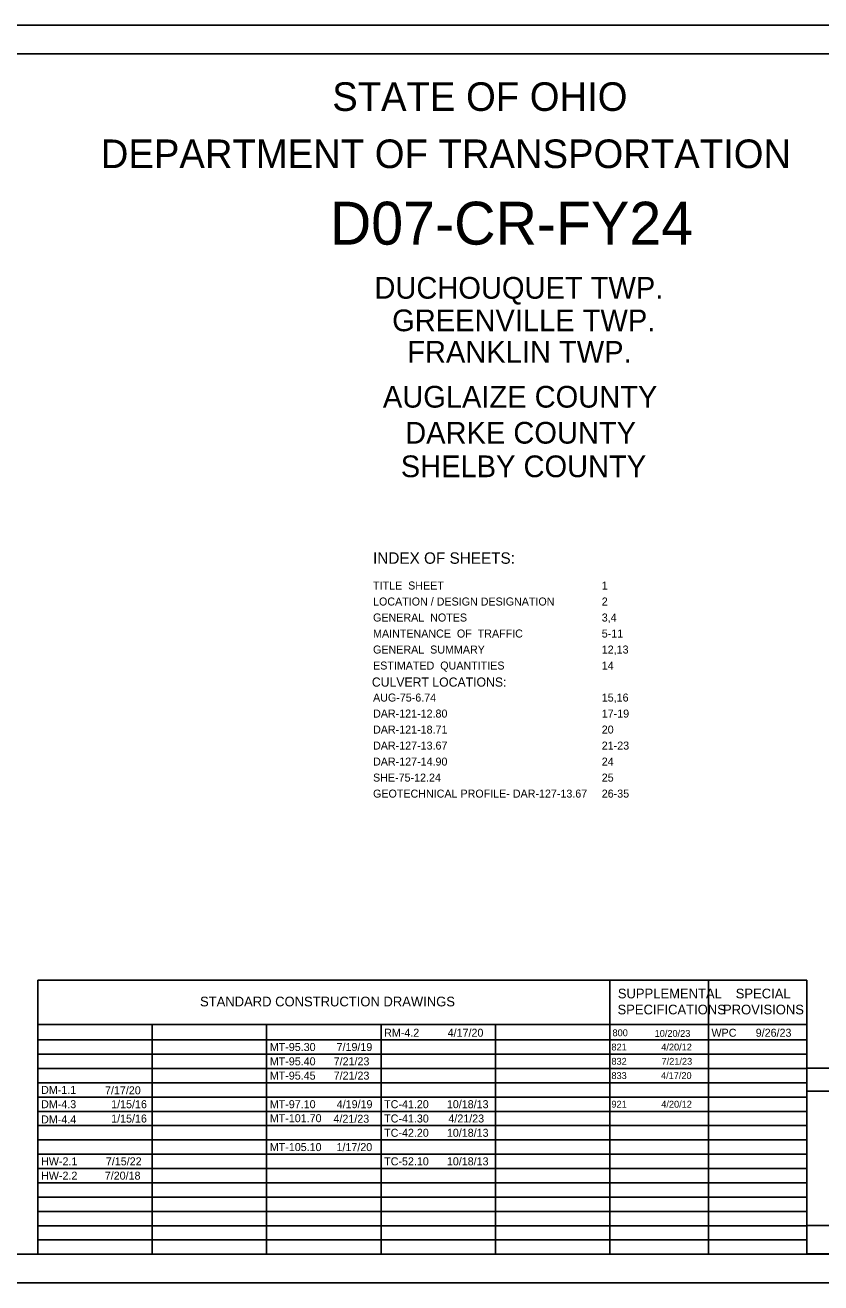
# Model space of a CAD drawing. Extents: x 0 to 34, y 0 to 22.
# Drawn here: x 8.42 to 22.34, y 0 to 22 of the extents above; entities that cross this region are included whole.
import ezdxf

# ---------------------------------------------------------------- set-up
doc = ezdxf.new("R2010")
doc.units = 0
for name, color, linetype in [('SH_Border', 7, 'Continuous'), ('SH_Cut_Line', 7, 'Continuous'), ('SH_Data', 7, 'Continuous'), ('SH_Text', 7, 'Continuous')]:
    doc.layers.add(name, color=color, linetype=linetype)

msp = doc.modelspace()

# ---------------------------------------------------------------- linework, layer by layer
at = {"layer": 'SH_Border'}
msp.add_lwpolyline([(1.5, 21.5), (33.5, 21.5), (33.5, 0.5), (1.5, 0.5)], close=True, dxfattribs=at)
at = {"layer": 'SH_Cut_Line'}
msp.add_lwpolyline([(0, 0), (34, 0), (34, 22), (0, 22)], close=True, dxfattribs=at)
at = {"layer": 'SH_Data'}
for p, q in [((8.648, 5.292), (22.098, 5.292)), ((8.648, 0.5), (8.648, 5.292)), ((8.648, 5.292), (22.098, 5.292)), ((8.648, 0.5), (8.648, 5.292)), ((18.648, 0.5), (18.648, 5.292)), ((18.648, 0.5), (18.648, 5.292)), ((20.373, 0.5), (20.373, 5.292)), ((20.373, 0.5), (20.373, 5.292)), ((22.098, 0.5), (22.098, 5.292)), ((22.098, 0.5), (22.098, 5.292)), ((8.648, 4.521), (22.098, 4.521)), ((8.648, 4.521), (22.098, 4.521)), ((10.648, 0.5), (10.648, 4.521)), ((10.648, 0.5), (10.648, 4.521)), ((12.648, 0.5), (12.648, 4.521)), ((12.648, 0.5), (12.648, 4.521)), ((14.648, 0.5), (14.648, 4.521)), ((14.648, 0.5), (14.648, 4.521)), ((16.648, 0.5), (16.648, 4.521)), ((16.648, 0.5), (16.648, 4.521)), ((8.648, 4.25), (22.098, 4.25)), ((8.648, 4.25), (22.098, 4.25)), ((8.648, 4), (22.098, 4)), ((8.648, 4), (22.098, 4)), ((8.648, 3.75), (22.098, 3.75)), ((8.648, 3.75), (22.098, 3.75)), ((22.098, 0.505), (22.098, 3.755)), ((22.098, 3.755), (24.898, 3.755)), ((8.648, 3.5), (22.098, 3.5)), ((8.648, 3.5), (22.098, 3.5)), ((22.098, 3.355), (24.898, 3.355)), ((8.648, 3.25), (22.098, 3.25)), ((8.648, 3.25), (22.098, 3.25)), ((8.648, 3), (22.098, 3)), ((8.648, 3), (22.098, 3)), ((8.648, 2.75), (22.098, 2.75)), ((8.648, 2.75), (22.098, 2.75)), ((8.648, 2.5), (22.098, 2.5)), ((8.648, 2.5), (22.098, 2.5)), ((8.648, 2.25), (22.098, 2.25)), ((8.648, 2.25), (22.098, 2.25)), ((8.648, 2), (22.098, 2)), ((8.648, 2), (22.098, 2)), ((8.648, 1.75), (22.098, 1.75)), ((8.648, 1.75), (22.098, 1.75)), ((8.648, 1.5), (22.098, 1.5)), ((8.648, 1.5), (22.098, 1.5)), ((8.648, 1.25), (22.098, 1.25)), ((8.648, 1.25), (22.098, 1.25)), ((8.648, 1), (22.098, 1)), ((8.648, 1), (22.098, 1)), ((8.648, 0.75), (22.098, 0.75)), ((8.648, 0.75), (22.098, 0.75)), ((22.098, 0.505), (24.898, 0.505))]:
    msp.add_line(p, q, dxfattribs=at)
msp.add_lwpolyline([(22.098, 0.505), (22.098, 1.005), (24.898, 1.005), (24.898, 0.505)], close=True, dxfattribs=at)

# ---------------------------------------------------------------- texts
for s, height, p in [('RM-4.2', 0.14, (14.703, 4.305)), ('4/17/20', 0.14, (15.814, 4.305)), ('800', 0.12, (18.697, 4.314)), ('10/20/23', 0.12, (19.434, 4.303)), ('WPC', 0.14, (20.428, 4.305)), ('9/26/23', 0.14, (21.202, 4.305)), ('MT-95.30', 0.14, (12.703, 4.055)), ('7/19/19', 0.14, (13.871, 4.055)), ('821', 0.12, (18.678, 4.065)), ('4/20/12', 0.12, (19.55, 4.065)), ('MT-95.40', 0.14, (12.703, 3.805)), ('7/21/23', 0.14, (13.82, 3.805)), ('832', 0.12, (18.678, 3.815)), ('7/21/23', 0.12, (19.555, 3.815)), ('MT-95.45', 0.14, (12.703, 3.555)), ('7/21/23', 0.14, (13.82, 3.555)), ('833', 0.12, (18.678, 3.565)), ('4/17/20', 0.12, (19.545, 3.565)), ('7/17/20', 0.14, (9.821, 3.298)), ('DM-4.3', 0.14, (8.703, 3.055)), ('1/15/16', 0.14, (9.929, 3.055)), ('MT-97.10', 0.14, (12.703, 3.055)), ('4/19/19', 0.14, (13.874, 3.055)), ('TC-41.20', 0.14, (14.703, 3.055)), ('10/18/13', 0.14, (15.8, 3.055)), ('921', 0.12, (18.678, 3.065)), ('4/20/12', 0.12, (19.55, 3.065)), ('DM-4.4', 0.14, (8.703, 2.789)), ('1/15/16', 0.14, (9.929, 2.804)), ('MT-101.70', 0.14, (12.703, 2.81)), ('4/21/23', 0.14, (13.817, 2.801)), ('TC-41.30', 0.14, (14.703, 2.805)), ('4/21/23', 0.14, (15.827, 2.805)), ('TC-42.20', 0.14, (14.703, 2.555)), ('10/18/13', 0.14, (15.8, 2.555)), ('MT-105.10', 0.14, (12.703, 2.305)), ('1/17/20', 0.14, (13.87, 2.305)), ('7/15/22', 0.14, (9.836, 2.055)), ('10/18/13', 0.14, (15.8, 2.055)), ('HW-2.1', 0.14, (8.703, 2.055)), ('TC-52.10', 0.14, (14.703, 2.055)), ('HW-2.2', 0.14, (8.703, 1.805)), ('7/20/18', 0.14, (9.817, 1.805))]:
    msp.add_text(s, height=height, dxfattribs=at).set_placement(p)
at = {"layer": 'SH_Text'}
for s, height, p in [('STATE OF OHIO', 0.5, (13.795, 20.5)), ('STATE OF OHIO', 0.5, (13.795, 20.5)), ('DEPARTMENT OF TRANSPORTATION', 0.5, (9.747, 19.5)), ('DEPARTMENT OF TRANSPORTATION', 0.5, (9.747, 19.5)), ('D07-CR-FY24', 0.75, (13.753, 18.161)), ('DUCHOUQUET TWP.', 0.38, (14.533, 17.215)), ('GREENVILLE TWP.', 0.38, (14.843, 16.646)), ('FRANKLIN TWP.', 0.38, (15.107, 16.095)), ('AUGLAIZE COUNTY', 0.38, (14.681, 15.31)), ('DARKE COUNTY', 0.38, (15.071, 14.68)), ('SHELBY COUNTY', 0.38, (14.994, 14.093)), ('INDEX OF SHEETS:', 0.2, (14.509, 12.578)), ('INDEX OF SHEETS:', 0.2, (14.509, 12.578)), ('TITLE  SHEET', 0.14, (14.509, 12.128)), ('1', 0.14, (18.509, 12.128)), ('LOCATION / DESIGN DESIGNATION', 0.14, (14.509, 11.848)), ('2', 0.14, (18.509, 11.848)), ('GENERAL  NOTES', 0.14, (14.509, 11.568)), ('3,4', 0.14, (18.509, 11.568)), ('MAINTENANCE  OF  TRAFFIC', 0.14, (14.509, 11.288)), ('5-11', 0.14, (18.509, 11.288)), ('GENERAL  SUMMARY', 0.14, (14.509, 11.008)), ('12,13', 0.14, (18.509, 11.008)), ('ESTIMATED  QUANTITIES', 0.14, (14.509, 10.728)), ('14', 0.14, (18.509, 10.728)), ('CULVERT LOCATIONS: ', 0.16, (14.488, 10.429)), ('AUG-75-6.74', 0.14, (14.509, 10.168)), ('15,16', 0.14, (18.509, 10.168)), ('DAR-121-12.80', 0.14, (14.509, 9.888)), ('17-19', 0.14, (18.509, 9.888)), ('DAR-121-18.71', 0.14, (14.509, 9.608)), ('20', 0.14, (18.509, 9.608)), ('DAR-127-13.67', 0.14, (14.509, 9.328)), ('21-23', 0.14, (18.509, 9.328)), ('DAR-127-14.90', 0.14, (14.509, 9.048)), ('24', 0.14, (18.509, 9.048)), ('SHE-75-12.24', 0.14, (14.509, 8.768)), ('25', 0.14, (18.509, 8.768)), ('GEOTECHNICAL PROFILE- DAR-127-13.67', 0.14, (14.509, 8.488)), ('26-35', 0.14, (18.509, 8.488)), ('SUPPLEMENTAL', 0.17, (18.79, 4.976)), ('SUPPLEMENTAL', 0.17, (18.79, 4.976)), ('SPECIAL', 0.17, (20.852, 4.976)), ('SPECIAL', 0.17, (20.852, 4.976)), ('STANDARD CONSTRUCTION DRAWINGS', 0.17, (11.483, 4.836)), ('STANDARD CONSTRUCTION DRAWINGS', 0.17, (11.483, 4.836)), ('SPECIFICATIONS', 0.17, (18.785, 4.696)), ('SPECIFICATIONS', 0.17, (18.785, 4.696)), ('PROVISIONS', 0.17, (20.63, 4.696)), ('PROVISIONS', 0.17, (20.63, 4.696)), ('DM-1.1', 0.14, (8.703, 3.305))]:
    msp.add_text(s, height=height, dxfattribs=at).set_placement(p)

doc.saveas('drawing.dxf')
